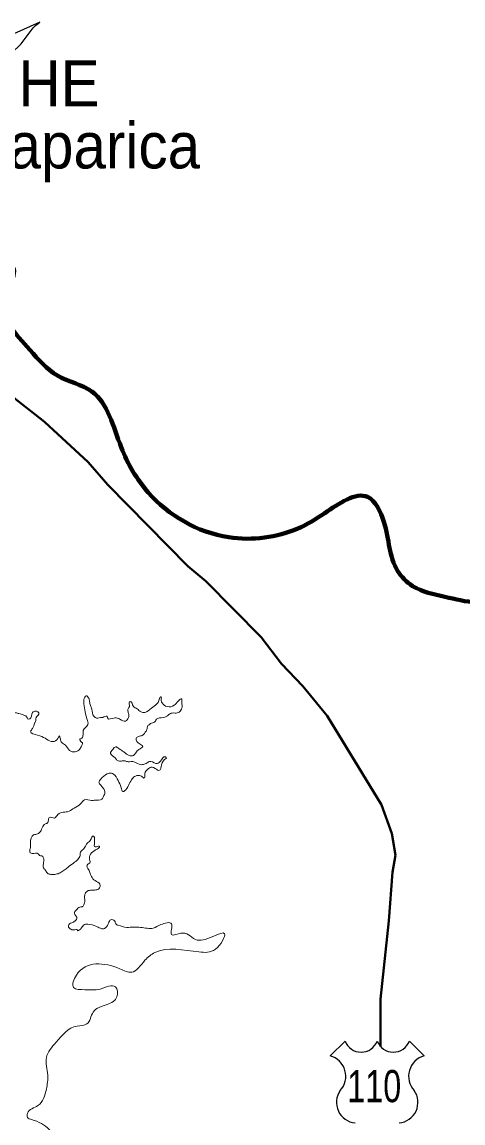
# Model space of a CAD drawing. Extents: x 553962 to 842807, y 8883888 to 9032388.
# Drawn here: x 579563 to 584357, y 8979171 to 8991142 of the extents above; entities that cross this region are included whole.
import ezdxf
from ezdxf.enums import TextEntityAlignment as Align

# ---------------------------------------------------------------- set-up
doc = ezdxf.new("R2010")
doc.units = 0
doc.header["$LTSCALE"] = 200
for name, color, linetype, lineweight in [('12', 7, 'Continuous', 25), ('25', 7, 'Continuous', 13), ('48', 7, 'Continuous', 25), ('50', 7, 'Continuous', 80), ('54', 7, 'Continuous', 25)]:
    doc.layers.add(name, color=color, linetype=linetype, lineweight=lineweight)
doc.layers.add('42', color=7, linetype='Continuous')

msp = doc.modelspace()

# ---------------------------------------------------------------- linework, layer by layer
at = {"layer": '12', "lineweight": 40}
msp.add_lwpolyline([(577759.9, 8988875.8), (577832.5, 8988674.7), (577901.5, 8988571.1), (578184.7, 8988310.3), (578513.4, 8987946.2), (578671.2, 8987814.3), (579419.2, 8987100.9), (579808.1, 8986794.1), (580283, 8986357.3), (580496.3, 8986108), (581364.8, 8985224.5), (581561.3, 8985062.5), (582162.5, 8984452.7), (582384.7, 8984161.9), (582616.4, 8983918.8), (582880.2, 8983596.7), (583472.4, 8982628.4), (583582.5, 8982317.7), (583621.7, 8982083.2), (583591.6, 8981897.8), (583552.5, 8981370), (583461.7, 8980518.1), (583461.7, 8980001.2)], dxfattribs=at)
at = {"layer": '25'}
for points in [[(579970.3, 8983381.7), (579928.3, 8983326.2), (579913.3, 8983318.6), (579880.6, 8983319.8), (579816, 8983353.5), (579732.6, 8983386), (579656.6, 8983427.2), (579677.5, 8983461.2), (579700.7, 8983516.6), (579706.8, 8983528), (579715.1, 8983564.5), (579723.5, 8983590.9), (579747, 8983622.4), (579727.8, 8983646.2), (579713.9, 8983650), (579679, 8983632.2), (579647.2, 8983565.5), (579623.3, 8983566.7), (579619.4, 8983578), (579581.3, 8983606.8), (579528.2, 8983623), (579513.1, 8983626.7), (579471.5, 8983636.7), (579433.4, 8983665.5), (579440.4, 8983701.9), (579442.4, 8983737.2), (579441.2, 8983739.7), (579447, 8983768.6), (579413, 8983867.8), (579391.3, 8983892.9), (579318.5, 8983971.9), (579294.2, 8984005.8), (579301.2, 8984042.2), (579315.8, 8984077.5), (579343, 8984115.3), (579355.3, 8984132.9), (579360.2, 8984143)], [(580290.3, 8983788.7), (580262.3, 8983816.3), (580235.2, 8983772.2), (580237.1, 8983729.5), (580249.6, 8983642.7), (580269.5, 8983564.8), (580280.4, 8983502), (580228.5, 8983437.7), (580228.9, 8983411.3), (580225.6, 8983377.4), (580205.8, 8983349.7), (580190.8, 8983343.3), (580198.6, 8983327), (580199.9, 8983323.2), (580212.7, 8983309.5), (580216.4, 8983308.2), (580211.9, 8983275.5), (580188.6, 8983232.7), (580142.4, 8983206.2), (580080.6, 8983222.3), (580035.8, 8983278.8), (579995.2, 8983308.8), (579980.9, 8983344), (579975.5, 8983366.6), (579970.3, 8983381.7)], [(581134, 8983136.2), (581123.8, 8983150.6), (581105.6, 8983150.6), (581070.3, 8983105.8), (581052.9, 8983091.9), (581034.2, 8983079.3), (580963.5, 8983103), (580932.2, 8983091.6), (580892.3, 8983071.3), (580850.8, 8983067.4), (580790.1, 8983093.7), (580748.6, 8983101.1), (580717.2, 8983098.5), (580683.1, 8983107.2), (580642.9, 8983105.8), (580622.8, 8983104.5), (580595, 8983115.7), (580573.2, 8983143.3), (580544, 8983165.8), (580526.1, 8983187.2), (580550.7, 8983231.2), (580582.9, 8983261.5), (580614.6, 8983241.5), (580670.4, 8983206.5), (580700.9, 8983182.7), (580728.8, 8983167.7), (580775.3, 8983167.8), (580800.1, 8983195.5), (580833.5, 8983232.1), (580860.9, 8983248.5), (580877.1, 8983263.7), (580868.1, 8983274.9), (580826.2, 8983303.7), (580804.4, 8983335.1), (580804.2, 8983354), (580830.3, 8983372.9), (580870.4, 8983385.6), (580911.2, 8983432.2), (580924.6, 8983468.7), (580931.7, 8983493.9), (580954.2, 8983506.5), (580954.2, 8983507.8), (580996.7, 8983524.3), (581025.1, 8983560.8), (581056.3, 8983574.7), (581131.6, 8983588.8), (581158.9, 8983611.5), (581195.2, 8983628), (581227.9, 8983628), (581273, 8983638.2), (581301.3, 8983683.6), (581303.5, 8983703.7), (581299.1, 8983749), (581299.9, 8983784.2), (581260.8, 8983756), (581236.5, 8983729.9), (581217.9, 8983712.2), (581141.4, 8983698.2), (581085.5, 8983738.3), (581076.3, 8983772.2), (581072.1, 8983803.6), (581068.3, 8983802.3), (581051.3, 8983763.3), (581027.9, 8983726.8), (580969.4, 8983681.3), (580898.4, 8983634.6), (580856.8, 8983640.8), (580813.6, 8983674.6), (580774.3, 8983699.6), (580739.6, 8983752.3), (580732.1, 8983748.5), (580731.6, 8983699.5), (580718.1, 8983675.6), (580716, 8983641.6), (580725.3, 8983605.2), (580720.6, 8983578.8), (580689.7, 8983539.7), (580627.8, 8983560.9), (580572.3, 8983574.6), (580493.2, 8983574.3), (580490.4, 8983591.9), (580477.8, 8983595.6), (580476.5, 8983595.6), (580454, 8983585.5), (580401.3, 8983576.6), (580373.7, 8983572.7), (580343.3, 8983592.7), (580322.1, 8983669.4), (580307.7, 8983710.8), (580297.1, 8983754.8), (580290.3, 8983788.7)], [(579888.2, 8982493.8), (579915.9, 8982486.3), (579954.3, 8982525.4), (580074.6, 8982559.7), (580129.7, 8982594), (580199.2, 8982640.5), (580243.8, 8982685.9), (580319.4, 8982677.4), (580352, 8982681.2), (580431.1, 8982691.5), (580449.5, 8982723), (580464.1, 8982760.8), (580459.9, 8982787.2), (580418.9, 8982842.4), (580399.6, 8982877.5), (580413.1, 8982902.7), (580435.4, 8982927.9), (580511.4, 8982973.4), (580556.8, 8982964.7), (580606.8, 8982894.5), (580640.6, 8982816.6), (580660, 8982773.9), (580678.8, 8982781.5), (580720.7, 8982842), (580753.8, 8982901.2), (580786, 8982936.5), (580839.9, 8982949.2), (580880.4, 8982928), (580889.3, 8982920.5), (580898.7, 8982967), (580930.7, 8983017.4), (580964.4, 8983038.9), (581023.8, 8983016.4), (581049.1, 8983003.9), (581064.1, 8983011.5), (581075, 8983041.7), (581112.8, 8983122.3), (581134, 8983136.2)], [(580701.6, 8981295.5), (580609.5, 8981320.4), (580584.1, 8981335.4), (580569.8, 8981369.3), (580528.2, 8981380.5), (580503.6, 8981343.9), (580472.8, 8981294.8), (580447.8, 8981282.2), (580415.1, 8981287.1), (580367, 8981310.8), (580278.7, 8981332), (580253.6, 8981331.9), (580216.2, 8981301.6), (580199, 8981278.9), (580166.5, 8981262.5), (580166.4, 8981268.8), (580124.9, 8981269.9), (580087, 8981282.4), (580067.8, 8981308.7), (580071.3, 8981326.3), (580116.2, 8981351.6), (580143.6, 8981371.8), (580160.9, 8981394.5), (580132.5, 8981452.2), (580152.1, 8981485), (580191.9, 8981517.8), (580212, 8981521.6), (580220.8, 8981522.9), (580239.2, 8981553.1), (580246.1, 8981602.2), (580243.1, 8981637.4), (580255.2, 8981671.3), (580273.8, 8981692.8), (580318.9, 8981701.7), (580355.3, 8981703.1), (580396.6, 8981715.8), (580411, 8981767.4), (580357.7, 8981806.2), (580318.1, 8981851.3), (580280.5, 8981938), (580268.8, 8981964.3), (580279.8, 8981983.2), (580304.7, 8982007.2), (580300.7, 8982023.5), (580301.2, 8982078.8), (580347, 8982129.3), (580379.4, 8982149.5), (580399.3, 8982162.1), (580405.4, 8982177.2), (580371.5, 8982174.6), (580352.6, 8982177.1), (580351, 8982206), (580351.8, 8982233.6), (580344.8, 8982286.4), (580341, 8982290.2), (580305.2, 8982242.3), (580266.7, 8982207), (580252, 8982179.3), (580221.1, 8982140.2), (580196.4, 8982107.5), (580194.3, 8982079.8), (580171, 8982037), (580122.5, 8981996.6), (580061.6, 8981949.9), (580021.7, 8981919.6), (579976.9, 8981890.6), (579931.8, 8981875.3), (579877.8, 8981872.7), (579841.2, 8981886.4), (579814.3, 8981922.8), (579804.1, 8981932.8), (579792.4, 8981955.4), (579798.1, 8982001.9), (579794.8, 8982057.2), (579778.2, 8982074.8), (579751.8, 8982079.7), (579738.9, 8982098.6), (579674.8, 8982100.9), (579653.3, 8982109.6), (579649, 8982146.1), (579653.8, 8982162.4), (579654.3, 8982216.5), (579689.6, 8982303.3), (579732.2, 8982313.5), (579754.6, 8982328.7), (579781.6, 8982379.1), (579817.5, 8982423.2), (579832.5, 8982428.2), (579848.5, 8982453.4), (579859.3, 8982492.4), (579888.2, 8982493.8)], [(581113.2, 8977420.6), (581052, 8977586.8), (581044.4, 8977701), (581112.9, 8977822.7), (581219.3, 8977944.5), (581226.9, 8977959.7), (581325.8, 8977997.7), (581150.9, 8978172.7), (581059.6, 8978180.3), (580846.7, 8978073.8), (580823.9, 8977997.7), (580687, 8978020.5), (580474.1, 8978324.9), (580542.6, 8978644.5), (580633.8, 8978751), (580808.7, 8978933.6), (580808.7, 8978941.2), (580763.1, 8978956.4), (580603.4, 8978888), (580382.9, 8978773.8), (580109.1, 8978811.9), (579858.2, 8979101), (579668.1, 8979207.5), (579622.5, 8979230.4), (579622.5, 8979276), (579736.5, 8979359.7), (579827.8, 8979539.3), (579843, 8979691.5), (579827.8, 8979881.7), (579934.2, 8980049.1), (580162.3, 8980224.1), (580268.8, 8980246.9), (580337.2, 8980376.3), (580489.3, 8980460), (580595.8, 8980543.7), (580580.6, 8980650.2), (580413.3, 8980627.4), (580246, 8980619.8), (580124.3, 8980642.6), (580154.7, 8980779.6), (580626.2, 8980848), (580755.5, 8980810), (580899.9, 8980939.3), (581006.4, 8981023), (581485.5, 8981030.6), (581667.9, 8981061.1), (581765.3, 8981228.5), (581468.7, 8981160), (581309, 8981236.1), (581187.4, 8981220.9), (581187.4, 8981335), (581073.3, 8981327.4), (580989.7, 8981289.3), (580852.8, 8981297), (580701.6, 8981295.5)]]:
    msp.add_spline(points, degree=3, dxfattribs=at)
at = {"layer": '48'}
for p, q in [((582914.9, 8979901.3), (583074.8, 8980061.2)), ((583774.1, 8980061.2), (583934.1, 8979901.3))]:
    msp.add_line(p, q, dxfattribs=at)
for centre, radius, start, end in [((583249.6, 8980128.1), 187.2, 200.95927, 339.04073), ((583599.3, 8980128.1), 187.2, 200.95927, 339.04073), ((582852.8, 8979679.4), 230.3, 317.5721, 74.36886), ((583996.1, 8979679.4), 230.3, 105.62774, 222.4279), ((583206.3, 8979394.3), 224.7, 144.73733, 264.65778), ((583642.6, 8979394.3), 224.7, 275.34222, 35.26267)]:
    msp.add_arc(centre, radius, start, end, dxfattribs=at)
at = {"layer": '50'}
msp.add_spline([(579148.1, 8988779.9), (579427, 8987839.9), (579649.7, 8987577), (579947.7, 8987297.7), (580322.6, 8987124), (580641.3, 8986518.9), (580936.3, 8986026.1), (581809.9, 8985539.3), (582560.8, 8985634.2), (582854.8, 8985802.5), (583320, 8985978.1), (583497.4, 8985705.8), (583646, 8985174.6), (583809.8, 8985009.3), (584160.3, 8984891.9), (584506.5, 8984830.5), (584852.9, 8984779.2), (585005.6, 8984542.9), (584803.5, 8984108.8), (584639.8, 8983913.1), (584599.4, 8983537.5), (584729.3, 8983103.2), (585070.6, 8982685.9), (585499.3, 8982399.4), (586356, 8982146.8), (586773.3, 8982125), (586965.2, 8982183), (587325.6, 8981684), (587677.5, 8981302.2), (587697, 8981261.2), (587912.1, 8980805.2), (588105, 8980568.2), (588287, 8980265.3), (588583.7, 8979894.5), (589056.5, 8979892.1), (589388.6, 8979897), (589996.6, 8979846.7), (590255.5, 8979649.4), (590619.8, 8979440.2), (591083.3, 8979488.8), (591297.8, 8979729.5), (591445.7, 8979869.5), (591601.6, 8980238.2), (591583.8, 8980772.4), (591589.1, 8981158.8), (591632.8, 8981407.2), (591637.9, 8981778.3), (591638, 8981784.3)], degree=3, dxfattribs=at)
at = {"layer": '54'}
msp.add_line((579758.1, 8991142.1), (573009.7, 8988092.3), dxfattribs=at)
msp.add_spline([(579253.9, 8987881.3), (579399.3, 8988198.4), (579494.6, 8988433.7), (579157.4, 8988770.1), (579046.6, 8988989.6), (579086.6, 8989163.4), (579277.5, 8989332.4), (579337.7, 8989439.8), (579418, 8989583.1), (579533.4, 8989721.3), (579191.8, 8989551.9), (578904.9, 8989801.6), (579055, 8990491.7), (579235.8, 8990655.6), (579552.3, 8990906.6), (579738, 8991126.8), (579758.1, 8991142.1)], degree=3, dxfattribs=at)

# ---------------------------------------------------------------- texts
at = {"layer": '42', "width": 0.95}
for s, p in [('UHE', (579736.7, 8990226.1)), ('Itaparica', (580281.3, 8989550))]:
    msp.add_text(s, height=500, dxfattribs=at).set_placement(p, align=Align.CENTER)
at = {"layer": '48', "width": 0.75}
msp.add_text('110', height=350, dxfattribs=at).set_placement((583392.5, 8979396.6), align=Align.CENTER)

doc.saveas('drawing.dxf')
